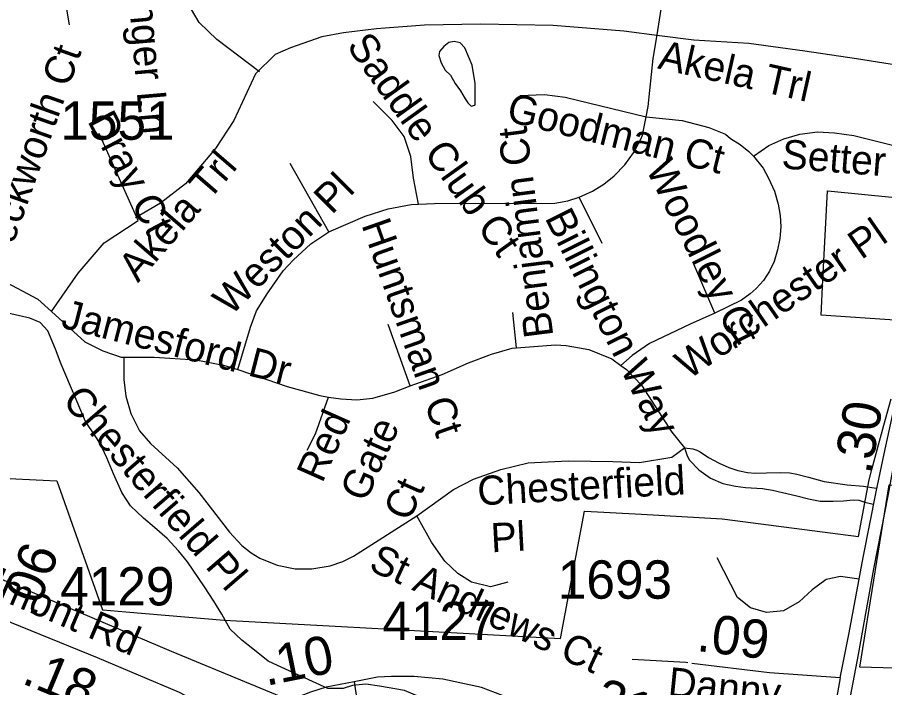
# Model space of a CAD drawing. Extents: x 1662474 to 1856135, y 779280 to 917889.
# Drawn here: x 1724517 to 1727341, y 831213 to 833398 of the extents above; entities that cross this region are included whole.
import ezdxf

# ---------------------------------------------------------------- set-up
doc = ezdxf.new("R2010")
doc.units = 0
for name, color, linetype in [('Exist Boundary Political City Limit New', 7, 'Continuous'), ('Exist Hydrographic Misc Water Feature', 7, 'Continuous'), ('Exist Hydrographic Pond Under 1500 Sq Ft', 7, 'Continuous'), ('Exist Road Non-System Type 51', 7, 'Continuous'), ('Exist Road Non-System Type 51 Label', 7, 'Continuous'), ('Exist Road Secondary Mileage Tenths English Label', 7, 'Continuous'), ('Exist Road Secondary Type 51 Attributed', 7, 'Continuous'), ('Exist Road Secondary Type 51 Divided Attributed', 7, 'Continuous'), ('Exist Road Secondary Type 51 Label', 7, 'Continuous'), ('Exist Road Secondary Type 51 Number Label', 7, 'Continuous'), ('Exist Utilities Electrical Transmission Line', 7, 'Continuous'), ('Map Preparation Boundary City Limit Buffer Line', 7, 'Continuous')]:
    doc.layers.add(name, color=color, linetype=linetype)

msp = doc.modelspace()

# ---------------------------------------------------------------- linework, layer by layer
at = {"layer": 'Exist Boundary Political City Limit New'}
for points in [[(1727389.6, 832410), (1727135.1, 832427.2), (1727140.2, 832541.9), (1727148.4, 832707), (1727154.9, 832832.4), (1727156.5, 832832.2), (1727276.9, 832820.2), (1727431.2, 832805.6)], [(1725190.4, 831433.2), (1725573.1, 831412.8), (1726285.4, 831373.6), (1726286.4, 831378.9), (1726364.4, 831789), (1726365.4, 831788.9), (1726549.1, 831778.2), (1726812.6, 831763.2), (1726854.1, 831757.9), (1727012.6, 831737.3), (1727256.6, 831705.6), (1727257.6, 831711.1), (1727269.5, 831775.4), (1727290.5, 831891), (1727299.9, 831924.6), (1727339.2, 832069.2), (1727362.8, 832154.9)], [(1722765.6, 831057.4), (1722813.1, 831263), (1722850, 831419.6), (1722890.8, 831592.3), (1722905, 831652.4), (1722917, 831703.2), (1722917.6, 831703.1), (1722934.6, 831696.6), (1722981.6, 831679), (1723164, 831609.5), (1723173.5, 831667.5), (1723194.4, 831794.1), (1723288, 831825.6), (1723636.5, 831970.3), (1723833.2, 831927.6), (1724020.8, 831917.3), (1724646, 831887.5), (1724794.4, 831467.4), (1724795.4, 831467.4), (1724870, 831460.9), (1725190.4, 831433.2)], [(1729142.6, 831829.8), (1729118.1, 831226.9), (1727260.9, 831280.2), (1727355.8, 831874.2), (1729142.6, 831829.8)]]:
    msp.add_lwpolyline(points, dxfattribs=at)
at = {"layer": 'Exist Hydrographic Misc Water Feature'}
for points in [[(1725126.1, 831542.3), (1725071.2, 831623), (1725041.5, 831658.9), (1725005.4, 831699), (1724963.7, 831735.1), (1724927.7, 831765.4), (1724885.8, 831805.7), (1724857.9, 831849.7), (1724830.3, 831910.1), (1724808.3, 831962.3), (1724786.6, 832008.7), (1724770.6, 832034.5), (1724739, 832080.2), (1724659.4, 832267.3), (1724641.8, 832316.9), (1724616.2, 832375.7), (1724592, 832403.3), (1724558.1, 832417.9), (1724510, 832428), (1724421.6, 832449.4)], [(1726112, 831052.8), (1726092.1, 831068.8), (1726030.2, 831097.2), (1725778.2, 831204), (1725696.4, 831218), (1725652.3, 831224.7), (1725608, 831220.6), (1725577.9, 831210.6), (1725528, 831210.8), (1725364.2, 831285.5), (1725334.3, 831300), (1725284.2, 831339.6), (1725248.4, 831368.3), (1725210.6, 831404.3), (1725182.7, 831452.5), (1725156.7, 831494.9), (1725126.1, 831542.3)]]:
    msp.add_lwpolyline(points, dxfattribs=at)
at = {"layer": 'Exist Hydrographic Pond Under 1500 Sq Ft'}
msp.add_lwpolyline([(1726008.5, 833115.2), (1726008.5, 833182.1), (1725998.2, 833242.2), (1725974.2, 833298.8), (1725958.7, 833314.3), (1725939.8, 833319.4), (1725922.7, 833316), (1725905.5, 833302.3), (1725891.8, 833286.8), (1725890, 833273.1), (1725896.9, 833249.1), (1725910.7, 833225), (1725927.8, 833209.6), (1725943.3, 833182.1), (1725960.4, 833158.1), (1725975.9, 833132.4), (1725984.5, 833118.6), (1725994.8, 833108.3), (1726006.8, 833111.8), (1726008.5, 833115.2)], dxfattribs=at)
at = {"layer": 'Exist Road Non-System Type 51'}
for p, q in [((1724911, 832735.9), (1724783.2, 833019.5)), ((1725532, 832698.5), (1725406, 832921.9)), ((1726421.2, 832660.2), (1726347, 832812.2)), ((1726788.4, 832433.2), (1726720.4, 832593.6)), ((1726143, 832321.1), (1726131, 832436.4)), ((1725796.6, 832196.4), (1725724.9, 832397))]:
    msp.add_line(p, q, dxfattribs=at)
for points in [[(1724686.6, 833373.6), (1724662.2, 833523.4), (1724658.9, 833585.9), (1724667.4, 833756.2)], [(1725305.2, 833220.6), (1725166.6, 833325.6), (1725109.5, 833380.7), (1725084, 833422.7), (1725054.2, 833482.2), (1725034.4, 833525.6), (1725017.6, 833599.9), (1725012.6, 833666.5), (1725016.6, 833724.5)], [(1726599.4, 833333.7), (1726623.6, 833487.2), (1726635.4, 833529.8)], [(1726564.6, 833073.4), (1726571.6, 833107.4), (1726587.1, 833263.9), (1726599.4, 833333.7)], [(1726153, 833143.4), (1726233.6, 833146), (1726301.4, 833137.1), (1726564.6, 833073.4)], [(1725823.1, 832788.9), (1725807.4, 832873.6), (1725798.9, 832943.7), (1725776.9, 833009), (1725737.9, 833061), (1725676.1, 833122.9)], [(1726347, 832812.2), (1726390, 832831.6), (1726426.8, 832854.2), (1726460.4, 832881.2), (1726494.8, 832916.9), (1726523.9, 832956.5), (1726547, 833000.4), (1726552.5, 833013.2), (1726564.6, 833073.4)], [(1726564.6, 833073.4), (1726682.4, 833061), (1726768.8, 833039.2), (1726822.9, 833017.4), (1726839.9, 833002.8), (1726870.6, 832983.6), (1726898.8, 832960.7), (1726914.6, 832945.8)], [(1726914.6, 832945.8), (1726964.5, 832980.1), (1727012.6, 833001.9), (1727065.6, 833017.4), (1727122.6, 833024.5), (1727178.1, 833021.4), (1727240.6, 833012.2), (1727406.2, 832971.8)], [(1726914.6, 832945.8), (1726945.4, 832906.2), (1726963.5, 832874.1), (1726982.6, 832830.9), (1726995, 832789.4), (1727001.6, 832752.4), (1727003, 832714.9), (1727000.2, 832677.2), (1726992.6, 832640.5), (1726981.1, 832602.2), (1726965.9, 832570.2), (1726946.6, 832540.5), (1726923.4, 832513.8), (1726903.6, 832496.2), (1726874.8, 832476), (1726788.4, 832433.2)], [(1725823.1, 832788.9), (1725875.4, 832791.4), (1726266.9, 832792.5), (1726309.4, 832800.1), (1726347, 832812.2)], [(1725532, 832698.5), (1725649.6, 832750.2), (1725724.6, 832773.4), (1725800, 832787.5), (1725823.1, 832788.9)], [(1724627.9, 832438.7), (1724715.5, 832563.7), (1724800.2, 832662.6), (1724911, 832735.9)], [(1725235.1, 832250), (1725275.9, 832388.6), (1725296.1, 832440.9), (1725331.2, 832496.2), (1725382.9, 832571.2), (1725415.8, 832606.4), (1725472.6, 832659.2), (1725532, 832698.5)], [(1724339.9, 832588.4), (1724465.6, 832542.4), (1724584, 832478.9), (1724627.9, 832438.7)], [(1724627.9, 832438.7), (1724737.2, 832340.5), (1724795.9, 832311.2), (1724855.6, 832289.9), (1724863.5, 832289.9)], [(1726788.4, 832433.2), (1726708.4, 832398.2), (1726575.9, 832335), (1726519.4, 832295.4), (1726482.4, 832263.4)], [(1725796.6, 832196.4), (1725900.2, 832233.8), (1725986.6, 832272), (1726060.9, 832299.9), (1726128.4, 832319.9), (1726143, 832321.1)], [(1726143, 832321.1), (1726269.2, 832330.6), (1726304.8, 832328.8), (1726378.1, 832315.4), (1726453.5, 832284.9), (1726482.4, 832263.4)], [(1724863.5, 832289.9), (1724963.2, 832290.2), (1725098.1, 832281.2), (1725188.5, 832263.9), (1725235.1, 832250)], [(1724863.5, 832289.9), (1724863.5, 832217.7), (1724870.9, 832163.4), (1724887.1, 832106.4), (1724915.2, 832049.8), (1724950.4, 832008.5), (1725037.6, 831930.1), (1725108.4, 831849.2), (1725208.1, 831720.1), (1725248.4, 831676.2), (1725279, 831652.9), (1725307.1, 831635.9), (1725362.8, 831612.8), (1725421.8, 831600.9), (1725476.6, 831600.2), (1725535.6, 831610.1), (1725577.1, 831624.2), (1725611.6, 831641.4), (1725817.9, 831773.4)], [(1726482.4, 832263.4), (1726500.8, 832249.8), (1726549.4, 832198.9), (1726648.2, 832046.1), (1726689.5, 831994.6)], [(1725235.1, 832250), (1725395.6, 832194.4), (1725502.6, 832164.9), (1725530.8, 832160.5)], [(1725530.8, 832160.5), (1725570.1, 832154.4), (1725622.4, 832151), (1725674.9, 832156.9), (1725746.8, 832177.9), (1725796.6, 832196.4)], [(1725461.1, 831987.2), (1725488.4, 832040.5), (1725530.8, 832160.5)], [(1725817.9, 831773.4), (1725937.5, 831859), (1726002.9, 831892.5), (1726091.6, 831923.8), (1726180.4, 831946.1), (1726310.5, 831952.6), (1726456.1, 831949.9), (1726542.8, 831946.9), (1726648.5, 831964.9), (1726689.5, 831994.6)], [(1726689.5, 831994.6), (1726716.9, 831991.6), (1726730.1, 831987.5), (1726740.1, 831981.7), (1726767.5, 831963.4), (1726802.4, 831944.4), (1726833.9, 831931.1), (1726863.8, 831921.1), (1726894.5, 831914.4), (1726920.1, 831912.8), (1726956.6, 831913.6), (1727001.5, 831914.4), (1727033, 831913.6), (1727055.4, 831908.7), (1727093.6, 831899.5), (1727144.2, 831885.4), (1727218.9, 831874.6), (1727272, 831869.7), (1727313.4, 831863.9)], [(1726689.5, 831994.6), (1726698.6, 831969.2), (1726706.1, 831954.2), (1726736, 831922.8), (1726774.1, 831896.2), (1726814.9, 831878.8), (1726855.5, 831870.5), (1726887.9, 831865.5), (1726943.4, 831862.2), (1726975.8, 831857.2), (1727055.4, 831838.1), (1727093.6, 831828.2), (1727131, 831820.7), (1727174.1, 831820.7), (1727207.4, 831822.4), (1727238.9, 831825.7), (1727257.1, 831824), (1727277, 831818.2), (1727303.8, 831811.5)], [(1726114.6, 831557.1), (1726058, 831542.1), (1725995.5, 831557.1), (1725951.4, 831585.4), (1725909.6, 831625.1), (1725865.9, 831687.5), (1725817.9, 831773.4)], [(1727258.6, 831567.2), (1727197.4, 831576), (1727150.9, 831566.2), (1727105.5, 831532.2), (1727063.5, 831492.6), (1727012.4, 831464.2), (1726956.6, 831457.9), (1726904.1, 831473.6), (1726862.1, 831507.2), (1726796, 831636.1)], [(1726700.8, 831294.7), (1726694.1, 831295.4), (1726519.1, 831305.6)]]:
    msp.add_lwpolyline(points, dxfattribs=at)
at = {"layer": 'Exist Road Secondary Type 51 Attributed'}
for points in [[(1727747.9, 833132.3), (1727571.9, 833198.6), (1727448.6, 833231.5), (1727249.3, 833262.4), (1727081.8, 833287.8), (1726899.2, 833312.1), (1726719.7, 833323), (1726607.8, 833337.8), (1726491.8, 833353.1), (1726261.7, 833371.2), (1726025.6, 833375.2), (1725843.5, 833372.7), (1725687.2, 833360), (1725579, 833347), (1725508.7, 833333.7), (1725406.4, 833298.5), (1725356.4, 833277.1), (1725293.2, 833213.9), (1725222.4, 833061), (1725162.2, 832970.2), (1725101.9, 832898.4), (1725064.2, 832855.4), (1724983.6, 832791.7), (1724902.2, 832744.7)], [(1724371.6, 831482.1), (1724496.8, 831425.6), (1724776.8, 831311.2), (1725044.6, 831199), (1725115.3, 831161), (1725164.4, 831124.8), (1725206.7, 831081.2)], [(1727196.2, 831245), (1726966.2, 831261.3), (1726713.5, 831291.7)], [(1727120.2, 830822.9), (1727026, 830831.1), (1726954.6, 830842.8), (1726837.6, 830869.6), (1726744.4, 830902.1), (1726667.7, 830936.8), (1726614.5, 830962.2), (1726537.8, 831013.4), (1726461.1, 831051.8), (1726405.7, 831068.8), (1726345.2, 831082.3), (1726275.8, 831103.6), (1726120.3, 831179.5), (1726028.7, 831213.5), (1725903, 831240.9), (1725809.2, 831250.3), (1725735.2, 831250.3), (1725690.4, 831247.2), (1725614.2, 831232.4)], [(1725614.2, 831232.4), (1725523.1, 831215), (1725472.1, 831198.4), (1725404.9, 831172.9), (1725334.7, 831142.8), (1725206.7, 831081.2)], [(1725614.2, 831232.4), (1725643.2, 831037.6), (1725648.2, 830882.1), (1725645.7, 830736.6)]]:
    msp.add_lwpolyline(points, dxfattribs=at)
at = {"layer": 'Exist Road Secondary Type 51 Divided Attributed'}
msp.add_line((1727196.2, 831245), (1727120.2, 830822.9), dxfattribs=at)
for points in [[(1727196.2, 831245), (1727225.7, 831391.8), (1727271, 831637.5), (1727313.5, 831851.7), (1727340.3, 831975.2), (1727399.3, 832249.7), (1727414.4, 832306), (1727459.7, 832436.4), (1727562.6, 832694.4), (1727747.9, 833132.3)], [(1727622.3, 832737), (1727601.7, 832677.9), (1727542.7, 832535.2), (1727485.1, 832392.4), (1727448, 832285.4), (1727432.9, 832230.5), (1727391.1, 832052), (1727352.6, 831843.4), (1727305.3, 831600.5), (1727255.2, 831321.8), (1727159.8, 830819.5)]]:
    msp.add_lwpolyline(points, dxfattribs=at)
at = {"layer": 'Exist Utilities Electrical Transmission Line'}
msp.add_lwpolyline([(1723473.3, 839431), (1723445.1, 838486.9), (1723411.2, 837570.7), (1723389.1, 836806.6), (1723380.6, 836578.5), (1723373.2, 836450.5), (1723288.7, 836219.4), (1723118.2, 835806.8), (1723048.4, 835651.6), (1723038.9, 835135.3), (1723035.3, 834803.2), (1723115.6, 834640.3), (1723184.2, 834509.4), (1723175.6, 834085.4), (1723164.6, 833613.2), (1723161, 833269.1), (1723159.4, 833121.1), (1723353.4, 832558.7), (1723518.7, 832096.9), (1723561.3, 831968.3), (1723624.9, 831919.6), (1723903.9, 831804.7), (1725017.8, 831332.8), (1725532.2, 831119.2)], dxfattribs=at)
at = {"layer": 'Map Preparation Boundary City Limit Buffer Line'}
for points in [[(1727389.6, 832410), (1727135.1, 832427.2), (1727140.2, 832541.9), (1727148.4, 832707), (1727154.9, 832832.4), (1727156.5, 832832.2), (1727276.9, 832820.2), (1727431.2, 832805.6)], [(1725190.4, 831433.2), (1725573.1, 831412.8), (1726285.4, 831373.6), (1726286.4, 831378.9), (1726364.4, 831789), (1726365.4, 831788.9), (1726549.1, 831778.2), (1726812.6, 831763.2), (1726854.1, 831757.9), (1727012.6, 831737.3), (1727256.6, 831705.6), (1727257.6, 831711.1), (1727269.5, 831775.4), (1727290.5, 831891), (1727299.9, 831924.6), (1727339.2, 832069.2), (1727362.8, 832154.9)], [(1722765.6, 831057.4), (1722813.1, 831263), (1722850, 831419.6), (1722890.8, 831592.3), (1722905, 831652.4), (1722917, 831703.2), (1722917.6, 831703.1), (1722934.6, 831696.6), (1722981.6, 831679), (1723164, 831609.5), (1723173.5, 831667.5), (1723194.4, 831794.1), (1723288, 831825.6), (1723636.5, 831970.3), (1723833.2, 831927.6), (1724020.8, 831917.3), (1724646, 831887.5), (1724794.4, 831467.4), (1724795.4, 831467.4), (1724870, 831460.9), (1725190.4, 831433.2)], [(1729142.6, 831829.8), (1729118.1, 831226.9), (1727260.9, 831280.2), (1727355.8, 831874.2), (1729142.6, 831829.8)]]:
    msp.add_lwpolyline(points, dxfattribs=at)

# ---------------------------------------------------------------- texts
at = {"layer": 'Exist Road Non-System Type 51 Label'}
for s, rotation, p in [('Camp Ranger Ln', 274.9668, (1724834.5, 833977.3)), ('Saddle Club Ct', 305.7378, (1725587.1, 833304)), ('Beckworth Ct', 70.4741, (1724474.6, 832574.4)), ('Goodman Ct', 346.0796, (1726106.2, 833060.5)), ('Dray Ct', 297.8101, (1724743.8, 833060.2)), ('Benjamin Ct', 97.2899, (1726262.8, 832359.5)), ('Setter Ct', 355.624, (1727003.9, 832905.7)), ('Woodley Ct', 296.5514, (1726562.1, 832905)), ('Weston Pl', 45.1042, (1725212.3, 832422.3)), ('Billington Way', 296.5514, (1726233.1, 832744.8)), ('Huntsman Ct', 289.4294, (1725637, 832721.7)), ('Worchester Pl', 34.7938, (1726702.8, 832215.4)), ('Jamesford Dr', 345.6104, (1724655.7, 832387.9)), ('Chesterfield Pl', 310.8175, (1724660.3, 832146.8)), ('Red', 66.0501, (1725510.1, 831877.2)), ('Gate', 66.0501, (1725651.8, 831814.3)), ('Chesterfield', 3.0776, (1726017.7, 831807.1)), ('Ct', 66.0501, (1725793.4, 831751.4)), (' Pl', 3.0776, (1726026, 831652.3)), ('St Andrews Ct', 335.2119, (1725657.3, 831598.5))]:
    msp.add_text(s, height=95, rotation=rotation, dxfattribs=at).set_placement(p)
at = {"layer": 'Exist Road Secondary Mileage Tenths English Label'}
for s, rotation, p in [('.30', 80.6465, (1727297.4, 831905.9)), ('.06', 69.3045, (1724572.6, 831436)), ('.09', 353.1469, (1726726.6, 831333.3)), ('.10', 11.4528, (1725327.3, 831218.8)), ('.18', 337.4852, (1724527.7, 831229.1)), ('.31', 339.1563, (1726340.7, 831148.7))]:
    msp.add_text(s, height=125, rotation=rotation, dxfattribs=at).set_placement(p)
at = {"layer": 'Exist Road Secondary Type 51 Label'}
for s, rotation, p in [('Akela Trl', 347.3568, (1726599.5, 833231.8)), ('Akela Trl', 49.1792, (1724909.9, 832530.7)), ('Woodmont Rd', 336.8731, (1724144.2, 831634.4)), ('Danny', 354.237, (1726633.2, 831186.2))]:
    msp.add_text(s, height=95, rotation=rotation, dxfattribs=at).set_placement(p)
at = {"layer": 'Exist Road Secondary Type 51 Number Label'}
for s, p in [('1551', (1724657.4, 832998.8)), ('1693', (1726277.2, 831503.2)), ('4129', (1724656.7, 831481.3)), ('4127', (1725705.9, 831368.3))]:
    msp.add_text(s, height=125, dxfattribs=at).set_placement(p)

doc.saveas('drawing.dxf')
